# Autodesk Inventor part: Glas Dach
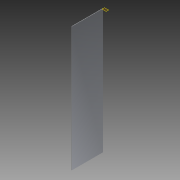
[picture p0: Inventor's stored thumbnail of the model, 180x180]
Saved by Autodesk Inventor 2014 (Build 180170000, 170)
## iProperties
Created: 2013-09
Part Number: Glas Dach
Material: Glas
Document SubType Name: Modeling
Designer: Stefan Tammegger
Mass: 76882.9 g
Surface Area: 56339.6 cm^2
Volume: 35267.4 cm^3
Density: 2.18 g/cm^3
Appearance: Klar
Author: Stefan Tammegger
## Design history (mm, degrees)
workplane "Arbeitsebene1"
sketch "Skizze1"
  geometry: L1 (-65.76, -840)-(-53, -840); L2 (-53, -840)-(-53, -10); L3 (-53, -10)-(-65.76, -10); L4 (-65.76, -10)-(-65.76, -840); L5 (-53, -5)-(-53, -30) reference; L6 (-57, -5)-(-53, -5) reference; L7 (-53, -845)-(-57, -845) reference; L8 (-53, -820)-(-53, -845) reference; 1 further point
  constraints: 8 end point, 2 parallel, 1 collinear, 1 horizontal, 1 perpendicular
  dimensions: "d0" = 12.76 distance of L2.end L3.end; "d1" = 5 distance between parallel lines of L6 L3; "d2" = 5 distance between parallel lines of L7 L1
  node "Referenz1"
  node "Referenz2"
  node "Referenz3"
  node "Referenz4"
workplane "Arbeitsebene2"
extrude "Extrusion1" new body sketch "Skizze1" stored distance "d3" = 10; taper "d4" = 0 deg
node "Volumenkörper1"
feature "쁕"
